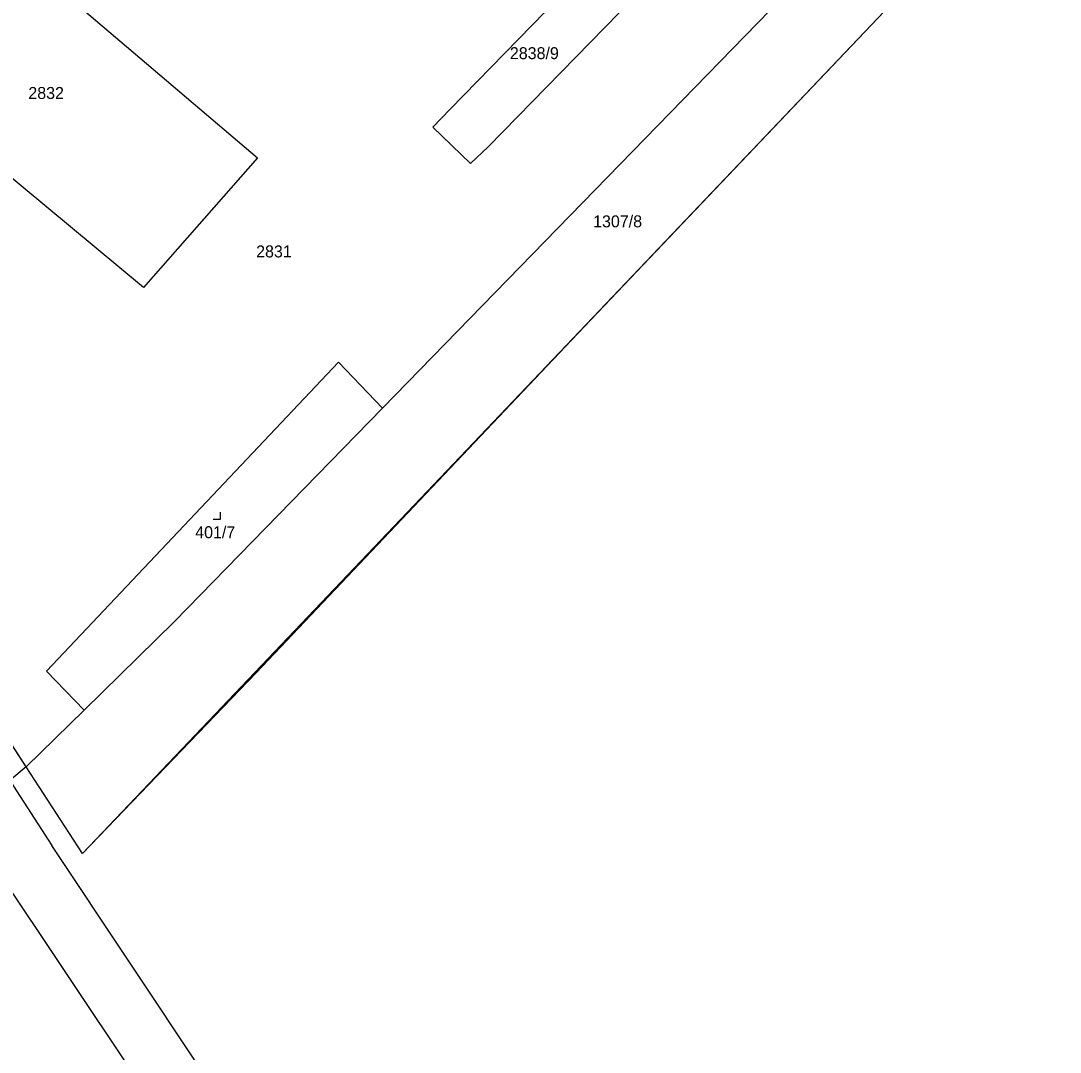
# Model space of a CAD drawing. Extents: x -580630 to -576196, y -1189024 to -1183567.
# Drawn here: x -577874.8 to -577727.2, y -1187195.1 to -1187048.7 of the extents above; entities that cross this region are included whole.
import ezdxf

# ---------------------------------------------------------------- set-up
doc = ezdxf.new("R2010")
doc.units = 0
for name, color, linetype in [('Vrstva 1', 7, 'Continuous'), ('Vrstva 18', 7, 'Continuous'), ('Vrstva 19', 7, 'Continuous'), ('Vrstva 25', 7, 'Continuous'), ('Vrstva 63', 7, 'Continuous')]:
    doc.layers.add(name, color=color, linetype=linetype)

msp = doc.modelspace()

# ---------------------------------------------------------------- linework, layer by layer
at = {"layer": 'Vrstva 1'}
for p, q in [((-577823.41, -1187103.68), (-577735.21, -1187013.14)), ((-577727.19, -1187021.13), (-577866, -1187166.92)), ((-577882.65, -1187032.88), (-577841.16, -1187068.17)), ((-577789.84, -1187036.7), (-577813.8, -1187061.25)), ((-577808.39, -1187066.6), (-577784.4, -1187042.01)), ((-577857.35, -1187086.58), (-577898.93, -1187052.03)), ((-577813.8, -1187061.25), (-577816.25, -1187063.83)), ((-577816.25, -1187063.83), (-577810.92, -1187068.99)), ((-577810.92, -1187068.99), (-577808.39, -1187066.6)), ((-577841.16, -1187068.17), (-577857.35, -1187086.58)), ((-577874, -1187154.58), (-577915.23, -1187090.96)), ((-577871.1, -1187141.01), (-577829.65, -1187097.15)), ((-577829.65, -1187097.15), (-577823.41, -1187103.68)), ((-577852.97, -1187134.03), (-577823.41, -1187103.68)), ((-577865.79, -1187146.56), (-577852.97, -1187134.03)), ((-577865.79, -1187146.56), (-577871.1, -1187141.01)), ((-577874, -1187154.58), (-577865.79, -1187146.56)), ((-577874, -1187154.58), (-577876.3, -1187156.53)), ((-577866, -1187166.92), (-577874, -1187154.58)), ((-577876.3, -1187156.53), (-577870.36, -1187165.75)), ((-577817.27, -1187260.15), (-577882.76, -1187162.29)), ((-577811.46, -1187254.07), (-577870.36, -1187165.75))]:
    msp.add_line(p, q, dxfattribs=at)
at = {"layer": 'Vrstva 25'}
msp.add_lwpolyline([(-577847.43, -1187119.45), (-577846.43, -1187119.45), (-577846.43, -1187118.45)], dxfattribs=at)
at = {"layer": 'Vrstva 63'}
for p, q in [((-577727.19, -1187021.13), (-577796.595, -1187094.025)), ((-577874, -1187154.58), (-577926.93, -1187073.35)), ((-577796.595, -1187094.025), (-577841.359, -1187141.241)), ((-577841.359, -1187141.241), (-577866, -1187166.92)), ((-577866, -1187166.92), (-577874, -1187154.58))]:
    msp.add_line(p, q, dxfattribs=at)

# ---------------------------------------------------------------- texts
at = {"layer": 'Vrstva 18'}
for s, p in [('2838/9', (-577805.327, -1187054.16)), ('2832', (-577873.695, -1187059.81)), ('1307/8', (-577793.508, -1187078.03)), ('2831', (-577841.353, -1187082.3))]:
    msp.add_text(s, height=1.7, dxfattribs=at).set_placement(p)
at = {"layer": 'Vrstva 19'}
msp.add_text('401/7', height=1.7, dxfattribs=at).set_placement((-577850.002, -1187122.15))

doc.saveas('drawing.dxf')
